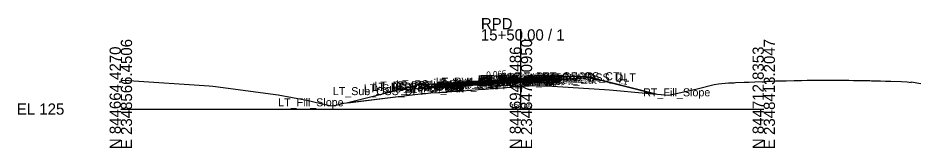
# Model space of a CAD drawing. Extents: x -26 to 2348536, y -510 to 844755.
# Drawn here: x -25.7 to 200, y 490.3 to 522.7 of the extents above; entities that cross this region are included whole.
import ezdxf

# ---------------------------------------------------------------- set-up
doc = ezdxf.new("R2010")
doc.units = 0
for name, color, linetype in [('Default', 7, 'Continuous'), ('Exist Cross Section Cell', 7, 'Continuous'), ('Exist XS Center Line Elevation Label', 7, 'Continuous'), ('Exist XS Ground Line', 7, 'Continuous'), ('Prop CMT Pvmt Course 1', 7, 'Continuous'), ('Prop CMT Pvmt Course 2', 7, 'Continuous'), ('Prop CMT Pvmt Course 3', 7, 'Continuous'), ('Prop CMT Pvmt Surface', 7, 'Continuous'), ('Prop CMT Pvmt Surface Shoulder', 7, 'Continuous'), ('Prop CMT Shld Paved Course 1', 7, 'Continuous'), ('Prop CMT Shld Paved Course 2', 7, 'Continuous'), ('Prop CMT Shld Paved Course 3', 7, 'Continuous'), ('Prop CMT Slope Grass', 7, 'Continuous'), ('Prop CMT Subgrade Earthwork', 7, 'Continuous'), ('Prop XS Earthwork Shape', 7, 'Continuous'), ('Prop XS SE Text', 7, 'Continuous'), ('Prop XS Side Slope Text', 7, 'Continuous'), ('Scratch_Level_0', 7, 'Continuous')]:
    doc.layers.add(name, color=color, linetype=linetype)

msp = doc.modelspace()

# ---------------------------------------------------------------- linework, layer by layer
at = {"layer": 'Exist Cross Section Cell'}
for p, q in [((100, 500), (100, 519.91)), ((0, 500), (100, 500)), ((100, 500), (160.71, 500))]:
    msp.add_line(p, q, dxfattribs=at)
at = {"layer": 'Exist XS Ground Line'}
msp.add_lwpolyline([(0, 507.18), (2, 507.09), (22.06, 505.78), (22.97, 505.72), (23.7, 505.64), (39.29, 503.58), (46.46, 502.22), (50.02, 501.42), (52.31, 500.93), (52.99, 500.79), (55.17, 501.3), (55.77, 501.45), (71.43, 503.39), (74.88, 503.82), (75.24, 503.85), (76.26, 503.91), (77.51, 504.03), (79.44, 504.14), (79.76, 504.16), (80.19, 504.19), (82.39, 504.35), (83.99, 504.47), (84.96, 504.55), (85.46, 504.58), (87.21, 504.7), (87.85, 504.75), (90.19, 504.94), (91.03, 505), (92.85, 505.13), (93.22, 505.16), (93.61, 505.21), (95.44, 505.33), (97.42, 505.47), (98.05, 505.52), (99.45, 505.62), (100, 505.66), (100.72, 505.71), (103.5, 505.86), (105.49, 505.83), (105.99, 505.81), (106.58, 505.8), (120.89, 504.88), (122.15, 504.8), (131.19, 503.97), (136.94, 503.47), (144.07, 505.08), (148.3, 506.16), (149.37, 506.26), (151.92, 506.52), (152.48, 506.52), (153.29, 506.58), (153.68, 506.6), (155.85, 506.69), (156.97, 506.74), (158.51, 506.8), (160.71, 506.89), (161.14, 506.91), (161.5, 506.93), (162.81, 507), (163.67, 507.01), (165.2, 507.06), (166.29, 507.08), (168.34, 507.13), (168.91, 507.14), (169.22, 507.15), (170.15, 507.16), (171.56, 507.18), (172.2, 507.19), (174.47, 507.23), (174.95, 507.23), (176.8, 507.24), (178.47, 507.23), (179.39, 507.22), (181.15, 507.21), (182, 507.19), (183.17, 507.17), (184.67, 507.14), (185.2, 507.13), (186.8, 507.1), (187.25, 507.09), (187.62, 507.08), (188.43, 507.06), (189.9, 507.03), (191.13, 507), (192.51, 506.95), (195.12, 506.86), (196.59, 506.78), (197.54, 506.67), (197.56, 506.77), (200, 506.41)], dxfattribs=at)
at = {"layer": 'Prop CMT Pvmt Course 1'}
for p, q in [((100, 507.63), (104, 507.89)), ((104, 507.89), (104, 507.64)), ((100, 507.63), (88, 506.85)), ((88, 506.6), (100, 507.38)), ((88, 506.85), (88, 506.6)), ((104, 507.64), (100, 507.38)), ((100, 507.38), (100, 507.63)), ((100, 507.38), (100, 507.63)), ((100, 507.38), (100, 507.51)), ((100, 507.51), (100, 507.51)), ((100, 507.51), (100, 507.38)), ((100, 507.38), (100, 507.51)), ((100, 507.51), (100, 507.51)), ((100, 507.51), (100, 507.38)), ((100, 507.38), (100, 507.38)), ((100, 507.38), (100, 507.38))]:
    msp.add_line(p, q, dxfattribs=at)
at = {"layer": 'Prop CMT Pvmt Course 2'}
for p, q in [((100, 507.38), (88, 506.6)), ((88, 506.27), (100, 507.05)), ((88, 506.6), (88, 506.27)), ((100, 507.38), (104, 507.64)), ((100, 507.05), (100, 507.38)), ((100, 507.05), (100, 507.38)), ((104, 507.31), (100, 507.05)), ((104, 507.64), (104, 507.31))]:
    msp.add_line(p, q, dxfattribs=at)
at = {"layer": 'Prop CMT Pvmt Course 3'}
for p, q in [((100, 507.05), (88, 506.27)), ((88, 505.94), (100, 506.72)), ((88, 506.27), (88, 505.94)), ((100, 507.05), (104, 507.31)), ((100, 506.72), (100, 507.05)), ((100, 506.72), (100, 507.05)), ((104, 506.98), (100, 506.72)), ((104, 507.31), (104, 506.98))]:
    msp.add_line(p, q, dxfattribs=at)
at = {"layer": 'Prop CMT Pvmt Surface'}
for q in [(104, 507.89), (88, 506.85)]:
    msp.add_line((100, 507.63), q, dxfattribs=at)
at = {"layer": 'Prop CMT Pvmt Surface Shoulder'}
for p, q in [((104, 507.89), (108, 508.15)), ((88, 506.85), (78, 506.2))]:
    msp.add_line(p, q, dxfattribs=at)
at = {"layer": 'Prop CMT Shld Paved Course 1'}
for p, q in [((104, 507.89), (108, 508.15)), ((108.23, 507.92), (104, 507.64)), ((104, 507.64), (104, 507.89)), ((108, 508.15), (108.23, 507.92)), ((77.73, 505.94), (88, 506.6)), ((78, 506.2), (77.73, 505.94)), ((88, 506.85), (78, 506.2)), ((88, 506.6), (88, 506.85))]:
    msp.add_line(p, q, dxfattribs=at)
at = {"layer": 'Prop CMT Shld Paved Course 2'}
for p, q in [((104, 507.64), (108.23, 507.92)), ((108.23, 507.92), (108.55, 507.61)), ((77.38, 505.58), (88, 506.27)), ((77.73, 505.94), (77.38, 505.58)), ((88, 506.6), (77.73, 505.94)), ((88, 506.27), (88, 506.6)), ((104, 507.31), (104, 507.64)), ((108.55, 507.61), (104, 507.31))]:
    msp.add_line(p, q, dxfattribs=at)
at = {"layer": 'Prop CMT Shld Paved Course 3'}
for p, q in [((76.52, 505.19), (88, 505.94)), ((77.38, 505.58), (76.88, 505.55)), ((88, 506.27), (77.38, 505.58)), ((88, 505.94), (88, 506.27)), ((104, 507.31), (108.55, 507.61)), ((109.36, 507.33), (104, 506.98)), ((104, 506.98), (104, 507.31)), ((108.55, 507.61), (109.05, 507.64)), ((109.05, 507.64), (109.36, 507.33)), ((76.88, 505.55), (76.52, 505.19))]:
    msp.add_line(p, q, dxfattribs=at)
at = {"layer": 'Prop CMT Slope Grass'}
for p, q in [((108, 508.15), (116, 508.19)), ((116, 508.19), (133.81, 503.74)), ((74, 505.88), (56.75, 501.57)), ((78, 506.2), (74, 505.88))]:
    msp.add_line(p, q, dxfattribs=at)
at = {"layer": 'Prop CMT Subgrade Earthwork'}
for p, q in [((109.36, 507.33), (117.39, 507.85)), ((88, 505.94), (76.52, 505.19)), ((100, 506.72), (88, 505.94)), ((100, 506.72), (104, 506.98)), ((104, 506.98), (109.36, 507.33)), ((76.52, 505.19), (69.37, 504.73))]:
    msp.add_line(p, q, dxfattribs=at)
at = {"layer": 'Prop XS Earthwork Shape'}
msp.add_lwpolyline([(69.37, 504.73), (56.75, 501.57), (71.43, 503.39), (74.88, 503.82), (75.24, 503.85), (76.26, 503.91), (77.51, 504.03), (79.44, 504.14), (79.76, 504.16), (80.19, 504.19), (82.39, 504.35), (83.99, 504.47), (84.96, 504.55), (85.46, 504.58), (87.21, 504.7), (87.85, 504.75), (90.19, 504.94), (91.03, 505), (92.85, 505.13), (93.22, 505.16), (93.61, 505.21), (95.44, 505.33), (97.42, 505.47), (98.05, 505.52), (99.45, 505.62), (100, 505.66), (100.72, 505.71), (103.5, 505.86), (105.49, 505.83), (105.99, 505.81), (106.58, 505.8), (120.89, 504.88), (122.15, 504.8), (131.19, 503.97), (133.81, 503.74), (117.39, 507.85), (109.36, 507.33), (104, 506.98), (100, 506.72), (88, 505.94), (76.52, 505.19)], close=True, dxfattribs=at)

# ---------------------------------------------------------------- texts
at = {"layer": 'Default'}
msp.add_text('-', height=0.0001, dxfattribs=at).set_placement((0, 500))
at = {"layer": 'Exist Cross Section Cell'}
for s, p in [('RPD', (90, 519.91)), ('15+50.00 / 1', (90, 517.11)), ('EL 125', (-26, 498.6))]:
    msp.add_text(s, height=2.8, dxfattribs=at).set_placement(p)
for s, p in [('E 2348566.4506', (2.8, 490)), ('E 2348471.0950', (102.8, 490)), ('E 2348413.2047', (163.51, 490)), ('N 844664.4270', (0, 490)), ('N 844694.5486', (100, 490)), ('N 844712.8353', (160.71, 490))]:
    msp.add_text(s, height=2.8, rotation=90, dxfattribs=at).set_placement(p)
at = {"layer": 'Exist XS Center Line Elevation Label'}
msp.add_text('130.66', height=1.2, dxfattribs=at).set_placement((97.45, 500.06))
at = {"layer": 'Prop XS SE Text'}
msp.add_text('0.065', height=1.5, rotation=3.719, dxfattribs=at).set_placement((91.42, 507.85))
at = {"layer": 'Prop XS Side Slope Text'}
for rotation, p in [(348.0249, (123.89, 506.56)), (14.0362, (63.53, 504.17))]:
    msp.add_text('4:1', height=1.5, rotation=rotation, dxfattribs=at).set_placement(p)
at = {"layer": 'Scratch_Level_0'}
for s, p in [('LT_PV1_OEOT', (78.74, 505.85)), ('RT_Sub_OEEOP', (89.17, 505.72)), ('LT_Sub_OEEOP', (89.21, 505.72)), ('RT_PV2_OEEOP', (89.26, 506.38)), ('RT_PV3_OEEOP', (89.26, 506.05)), ('LT_PV2_OEEOP', (89.31, 506.38)), ('LT_PV3_OEEOP', (89.31, 506.05)), ('RT_PV1_OEEOP', (89.83, 506.51)), ('LT_PV1_OEEOP', (89.87, 506.51)), ('RT_PV2_IEEOP', (89.91, 506.38)), ('LT_PV2_IEEOP', (89.95, 506.38)), ('RT_PV1_IEEOP', (90.47, 506.51)), ('LT_PV1_IEEOP', (90.52, 506.51)), ('RT_Sub_Trench_Out', (93.52, 506.33)), ('PV2_PGL', (93.91, 506.38)), ('RT_Sub_OEOT', (94.03, 505.98)), ('RT_PV2_OEOT', (94.13, 506.64)), ('RT_PV3_OEOT', (94.13, 506.31)), ('PV1_PGL', (94.47, 506.63)), ('RT_PV1_OEOT', (94.69, 506.89)), ('RT_PS3_Shelf_Out', (94.98, 506.64)), ('RT_PS2_OEOP', (98.42, 506.92)), ('RT_PS3_OEOP', (98.74, 506.61)), ('RT_PS1_OEOP', (98.76, 507.15)), ('RT_Sub_OSS_DLT', (105.24, 506.88)), ('RT_GS_OS_CTL', (105.32, 507.19)), ('LT_Sub_OSS_DLT', (52.98, 503.48)), ('LT_Sub_Trench_Out', (60.72, 504.19)), ('LT_PS3_Shelf_Out', (62.86, 504.55)), ('LT_GS_OS_CTL', (63.37, 504.88)), ('LT_PS3_OEOP', (67.61, 504.58)), ('LT_PS2_OEOP', (67.97, 504.94)), ('LT_PS1_OEOP', (68.8, 505.2)), ('LT_Sub_OEOT', (78.08, 504.94)), ('LT_PV2_OEOT', (78.17, 505.6)), ('LT_PV3_OEOT', (78.17, 505.27)), ('RT_Fill_Slope', (130.55, 503.18)), ('LT_Fill_Slope', (39.33, 500.69))]:
    msp.add_text(s, height=2, dxfattribs=at).set_placement(p)

doc.saveas('drawing.dxf')
